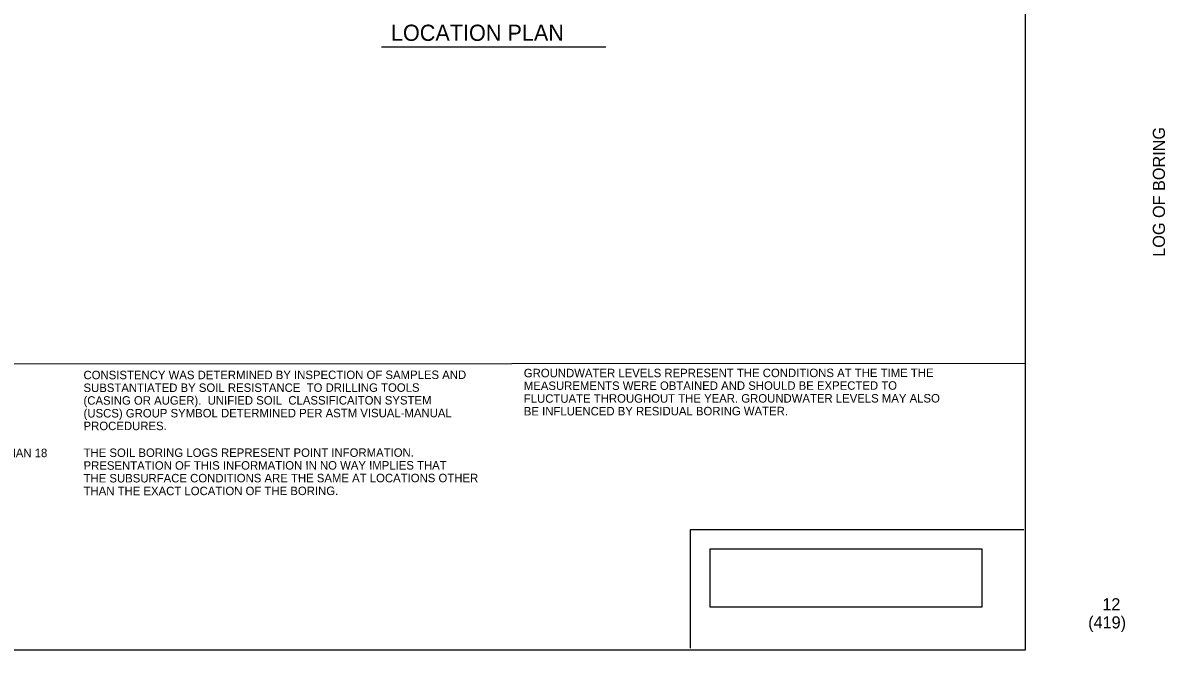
# Model space of a CAD drawing. Extents: x 19007.1 to 19038.2, y 21497.8 to 21516.9.
# Drawn here: x 19024.08 to 19038.21, y 21497.79 to 21505.55 of the extents above; entities that cross this region are included whole.
import ezdxf

# ---------------------------------------------------------------- set-up
doc = ezdxf.new("R2010")
doc.units = 0
for name, color, linetype in [('BORDER', 7, 'Continuous'), ('C-ANNO-TEXT', 7, 'Continuous'), ('G-ANNO-TTLB', 7, 'Continuous'), ('Level 1', 7, 'Continuous'), ('TYPICAL_TEXT_DIMEN_PR', 7, 'Continuous')]:
    doc.layers.add(name, color=color, linetype=linetype)

msp = doc.modelspace()

# ---------------------------------------------------------------- linework, layer by layer
at = {"layer": 'C-ANNO-TEXT'}
msp.add_line((19028.514, 21505.25), (19031.291, 21505.25), dxfattribs=at)
at = {"layer": 'G-ANNO-TTLB'}
for p, q in [((19036.464, 21499.275), (19032.336, 21499.275)), ((19032.336, 21499.275), (19032.336, 21497.81))]:
    msp.add_line(p, q, dxfattribs=at)
msp.add_lwpolyline([(19036.479, 21497.785), (19007.136, 21497.785), (19007.136, 21516.9), (19036.479, 21516.9)], close=True, dxfattribs=at)
at = {"layer": 'Level 1'}
msp.add_line((19007.136, 21501.315), (19036.486, 21501.336), dxfattribs=at)
msp.add_line((19007.136, 21501.315), (19036.486, 21501.336), dxfattribs=at)
at = {"layer": 'TYPICAL_TEXT_DIMEN_PR'}
msp.add_lwpolyline([(19032.579, 21498.323), (19035.947, 21498.323), (19035.947, 21499.036), (19032.579, 21499.036)], close=True, dxfattribs=at)

# ---------------------------------------------------------------- texts
at = {"layer": 'BORDER'}
for s, p in [('CONSISTENCY WAS DETERMINED BY INSPECTION OF SAMPLES AND ', (19024.828, 21501.137)), ('GROUNDWATER LEVELS REPRESENT THE CONDITIONS AT THE TIME THE ', (19030.276, 21501.161)), ('SUBSTANTIATED BY SOIL RESISTANCE  TO DRILLING TOOLS ', (19024.828, 21500.979)), ('MEASUREMENTS WERE OBTAINED AND SHOULD BE EXPECTED TO ', (19030.276, 21501.004)), ('(CASING OR AUGER).  UNIFIED SOIL  CLASSIFICAITON SYSTEM ', (19024.828, 21500.822)), ('FLUCTUATE THROUGHOUT THE YEAR. GROUNDWATER LEVELS MAY ALSO ', (19030.276, 21500.846)), ('BE INFLUENCED BY RESIDUAL BORING WATER. ', (19030.276, 21500.689)), ('(USCS) GROUP SYMBOL DETERMINED PER ASTM VISUAL-MANUAL ', (19024.829, 21500.664)), ('PROCEDURES.', (19024.829, 21500.507)), ('WHERE THE SAMPLER IS DRIVEN DISTANCES OTHER THAN 18 ', (19020.098, 21500.17)), ('THE SOIL BORING LOGS REPRESENT POINT INFORMATION. ', (19024.829, 21500.175)), ('PRESENTATION OF THIS INFORMATION IN NO WAY IMPLIES THAT ', (19024.829, 21500.017)), ('THE SUBSURFACE CONDITIONS ARE THE SAME AT LOCATIONS OTHER ', (19024.829, 21499.86)), ('THAN THE EXACT LOCATION OF THE BORING.', (19024.829, 21499.702))]:
    msp.add_text(s, height=0.10498, rotation=0.0399, dxfattribs=at).set_placement(p)
at = {"layer": 'C-ANNO-TEXT'}
msp.add_text('LOCATION PLAN', height=0.2, dxfattribs=at).set_placement((19028.632, 21505.324))
at = {"layer": 'G-ANNO-TTLB'}
msp.add_text('LOG OF BORING', height=0.15, rotation=90, dxfattribs=at).set_placement((19038.209, 21502.653))
for s, p in [('12', (19037.434, 21498.278)), ('(419)', (19037.259, 21498.054))]:
    msp.add_text(s, height=0.15, dxfattribs=at).set_placement(p)

doc.saveas('drawing.dxf')
